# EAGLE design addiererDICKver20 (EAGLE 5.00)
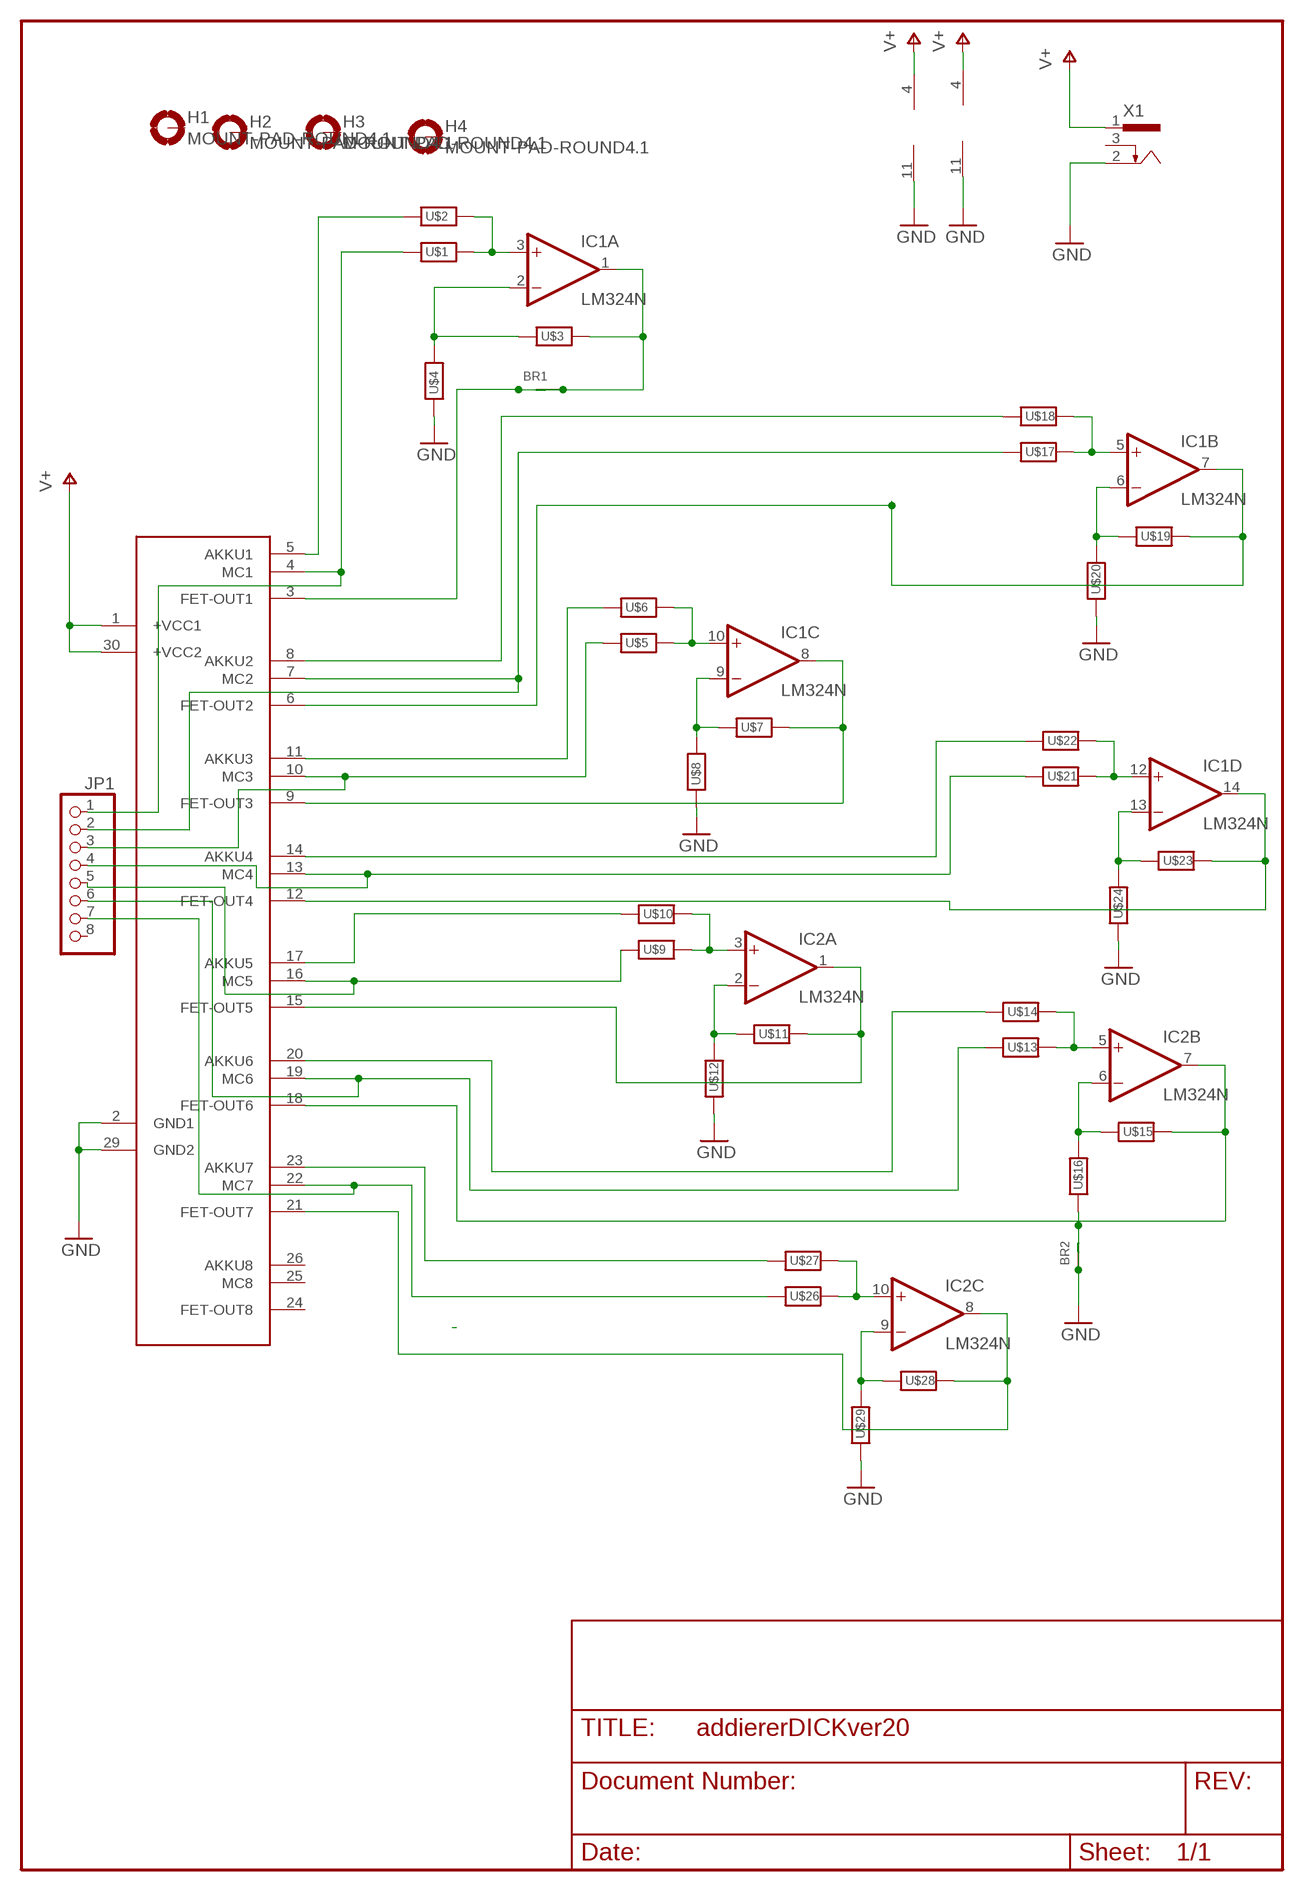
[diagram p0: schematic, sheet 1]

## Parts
BR1  BRUE3E  [BRUE3E]
BR2  BRUE8E  [BRUE8E]
H1  MOUNT-PAD-ROUND4.1  [4,1-PAD]
H2  MOUNT-PAD-ROUND4.1  [4,1-PAD]
H3  MOUNT-PAD-ROUND4.1  [4,1-PAD]
H4  MOUNT-PAD-ROUND4.1  [4,1-PAD]
IC1  LM324N  [DIL14]
IC2  LM324N  [DIL14]
JP1  PINHD-1X8  [1X08]
U$1  R4E  [R-4E]
U$2  R4E  [R-4E]
U$3  R4E  [R-4E]
U$4  R4E  [R-4E]
U$5  R4E  [R-4E]
U$6  R4E  [R-4E]
U$7  R4E  [R-4E]
U$8  R4E  [R-4E]
U$9  R4E  [R-4E]
U$10  R4E  [R-4E]
U$11  R4E  [R-4E]
U$12  R4E  [R-4E]
U$13  R4E  [R-4E]
U$14  R4E  [R-4E]
U$15  R4E  [R-4E]
U$16  R4E  [R-4E]
U$17  R4E  [R-4E]
U$18  R4E  [R-4E]
U$19  R4E  [R-4E]
U$20  R4E  [R-4E]
U$21  R4E  [R-4E]
U$22  R4E  [R-4E]
U$23  R4E  [R-4E]
U$24  R4E  [R-4E]
U$25  BALANCER1  [1X30]
U$26  R4E  [R-4E]
U$27  R4E  [R-4E]
U$28  R4E  [R-4E]
U$29  R4E  [R-4E]
X1  733980-62  [733980-62]

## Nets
AKKU23: U$22.1 U$25.14(AKKU4)
AKKU56: U$2.1 U$25.5(AKKU1)
GND: BR2.1 BR2.2 IC1.11(P:V-) IC2.11(P:V-) U$4.1 U$8.1 U$12.1 U$16.1 U$20.1 U$24.1 U$25.2(GND1) U$25.29(GND2) U$29.1 X1.2
N$1: IC1.3(A:+IN) U$1.2 U$2.2
N$2: IC1.2(A:-IN) U$3.1 U$4.2
N$3: BR1.1 BR1.2 IC1.1(A:OUT) U$3.2 U$25.3(FET-OUT1)
N$4: IC1.10(C:+IN) U$5.2 U$6.2
N$5: IC1.9(C:-IN) U$7.1 U$8.2
N$6: IC1.8(C:OUT) U$7.2 U$25.9(FET-OUT3)
N$7: IC2.3(A:+IN) U$9.2 U$10.2
N$8: IC2.2(A:-IN) U$11.1 U$12.2
N$9: IC2.1(A:OUT) U$11.2 U$25.15(FET-OUT5)
N$10: IC2.5(B:+IN) U$13.2 U$14.2
N$11: IC2.6(B:-IN) U$15.1 U$16.2
N$12: IC2.7(B:OUT) U$15.2 U$25.18(FET-OUT6)
N$13: IC1.5(B:+IN) U$17.2 U$18.2
N$14: IC1.6(B:-IN) U$19.1 U$20.2
N$15: IC1.7(B:OUT) U$19.2 U$25.6(FET-OUT2)
N$16: IC1.12(D:+IN) U$21.2 U$22.2
N$17: IC1.13(D:-IN) U$23.1 U$24.2
N$18: IC1.14(D:OUT) U$23.2 U$25.12(FET-OUT4)
N$19: U$18.1 U$25.8(AKKU2)
N$22: U$6.1 U$25.11(AKKU3)
N$25: U$10.1 U$25.17(AKKU5)
N$28: U$14.1 U$25.20(AKKU6)
N$30: IC2.10(C:+IN) U$26.2 U$27.2
N$31: IC2.9(C:-IN) U$28.1 U$29.2
N$32: IC2.8(C:OUT) U$25.21(FET-OUT7) U$28.2
N$33: U$25.23(AKKU7) U$27.1
N$36: JP1.1 U$1.1 U$25.4(MC1)
N$37: JP1.2 U$17.1 U$25.7(MC2)
N$38: JP1.3 U$5.1 U$25.10(MC3)
N$39: JP1.4 U$21.1 U$25.13(MC4)
N$40: JP1.7 U$25.22(MC7) U$26.1
N$41: JP1.6 U$13.1 U$25.19(MC6)
N$42: JP1.5 U$9.1 U$25.16(MC5)
V+: IC1.4(P:V+) IC2.4(P:V+) U$25.1(+VCC1) U$25.30(+VCC2) X1.1
Unconnected: H1.B4,1(MOUNT) H2.B4,1(MOUNT) H3.B4,1(MOUNT) H4.B4,1(MOUNT) IC2.12(D:+IN) IC2.13(D:-IN) IC2.14(D:OUT) JP1.8 U$25.24(FET-OUT8) U$25.25(MC8) U$25.26(AKKU8) X1.3

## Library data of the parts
BR1 = raf_discrete:BRUE3E
BR2 = raf_discrete:BRUE8E
H1-H4 = holes:MOUNT-PAD-ROUND: MOUNTING PAD, round
IC1 IC2 = linear:LM324: OP AMP
JP1 = pinhead:PINHD-1X8: PIN HEADER
U$1-U$24 U$26-U$29 = raf_discrete:R: Standard-Widerstand 1/4W, Baugrößen 4e - 8e
U$25 = balancer-mega8:BALANCER1
X1 = con-conrad:73398?: FEMALE PRINT CONNECTOR Niedervolt-Steckverbinder Distributor Conrad

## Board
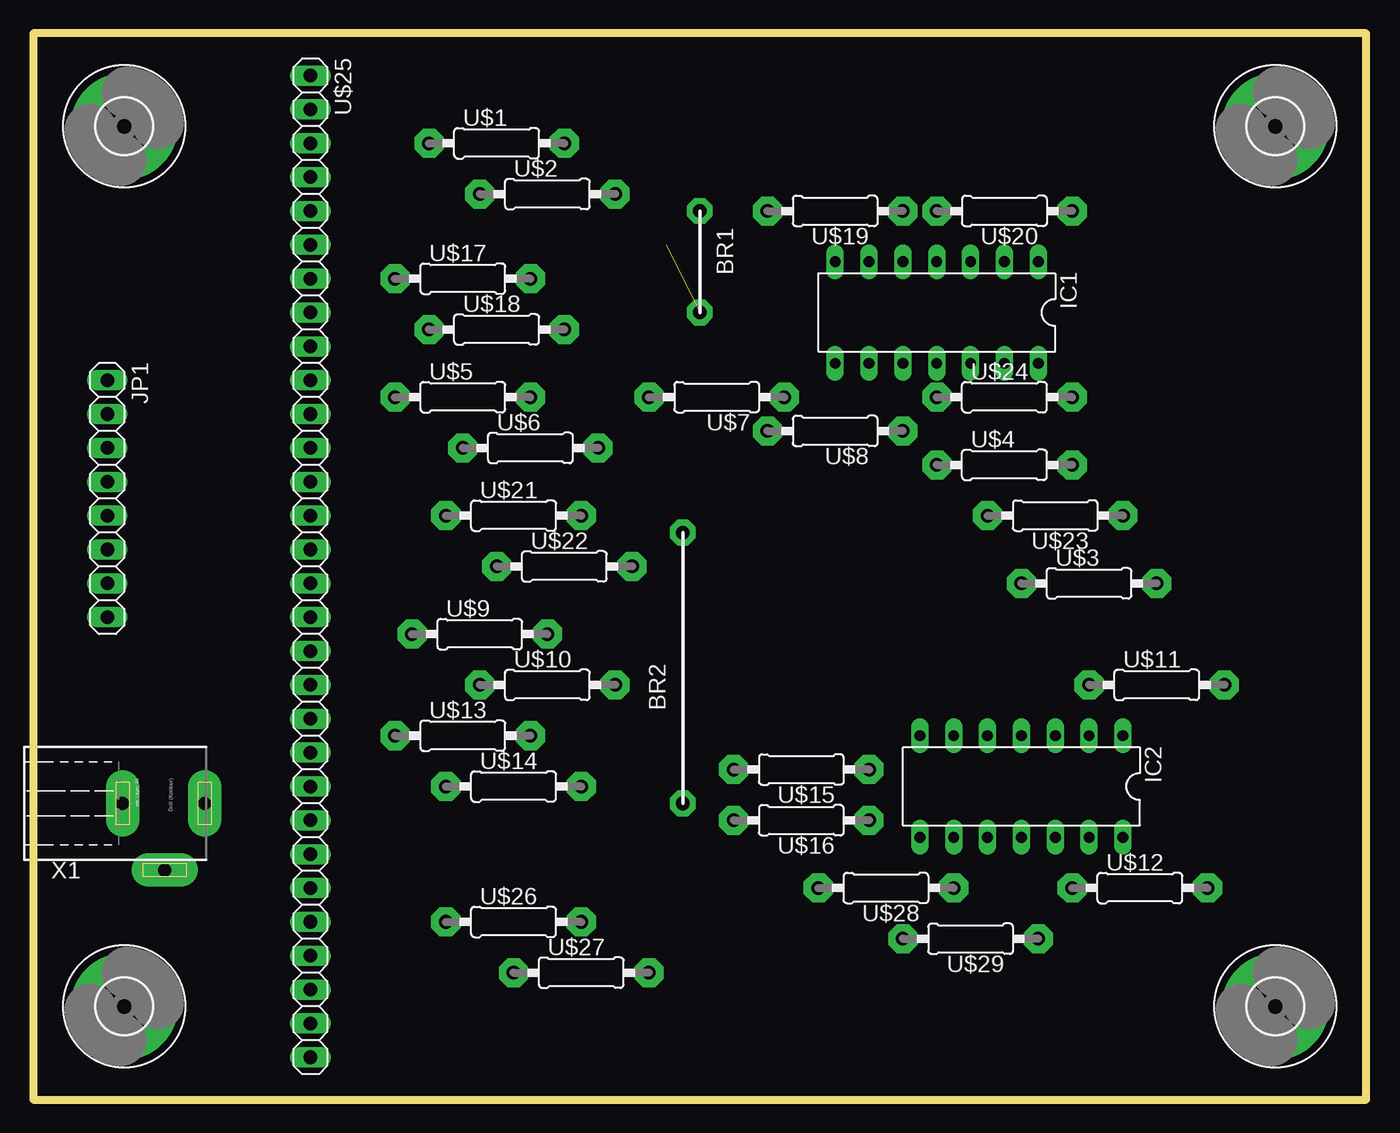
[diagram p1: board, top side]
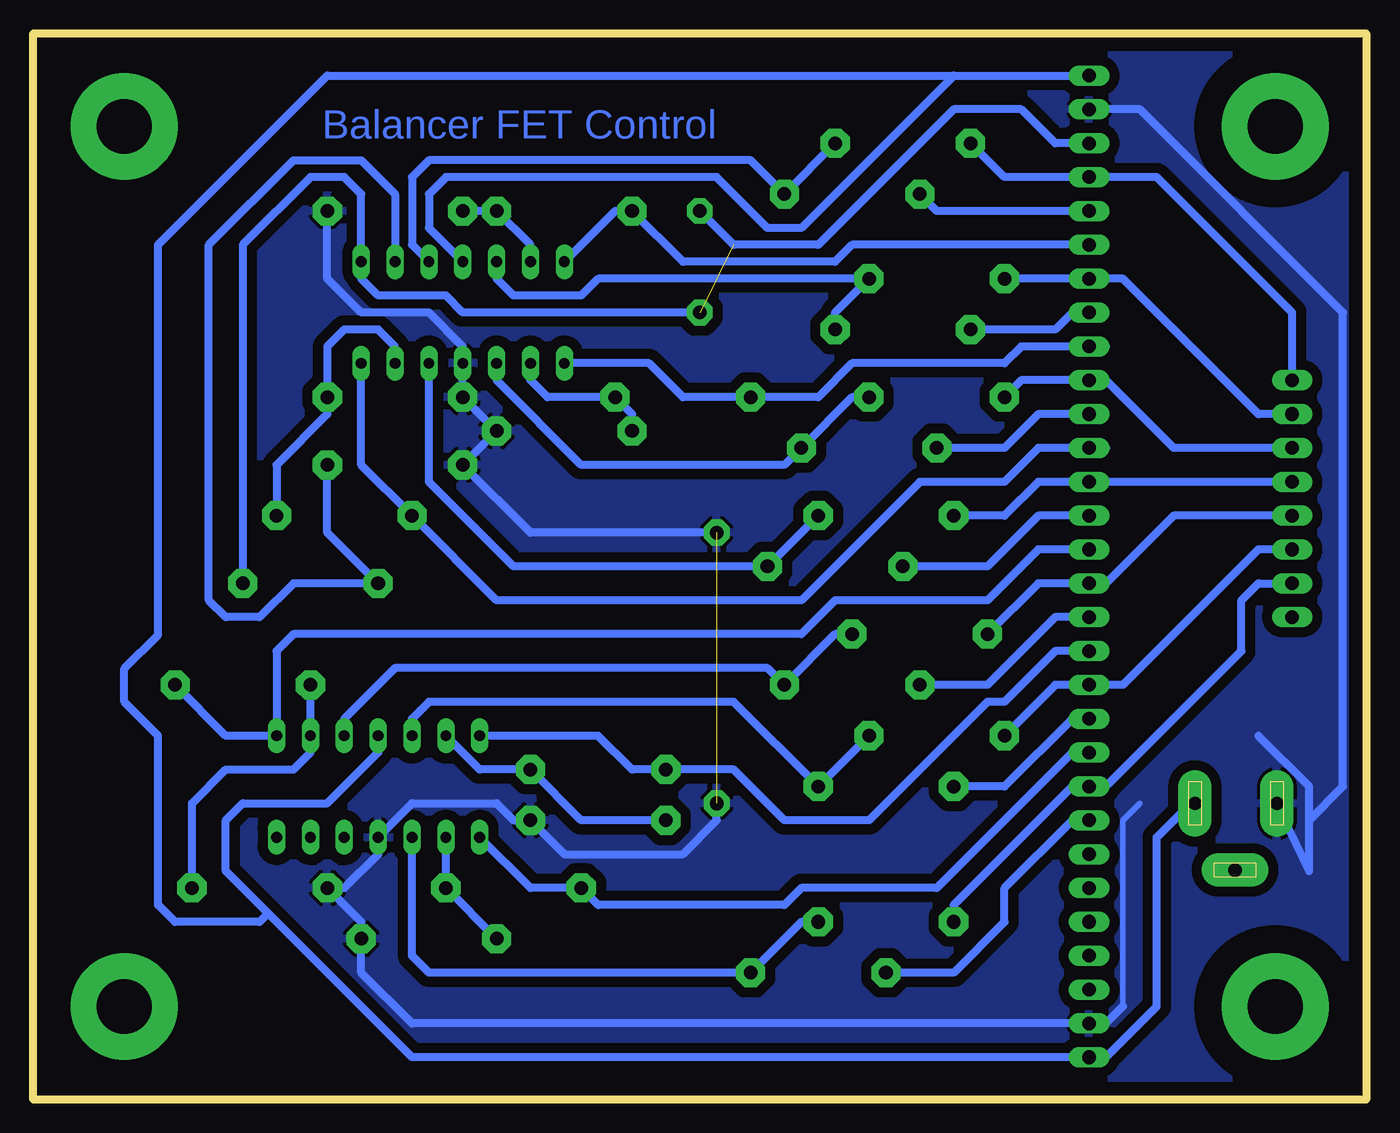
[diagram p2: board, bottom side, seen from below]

Size 100 x 80 mm. Coordinates in mm from the lower left corner, seen from the top.
Outline: 0,0 100,0 100,80 0,80 0,0
Copper layers (1*16): Top 0.035mm / dielectric 1.5mm / Bottom 0.035mm
Design rules "default *": minimum track width 10mil, minimum drill 24mil, track to track 30mil, track to pad 30mil, pad to pad 8mil, via to via 8mil, smd to smd 8mil, copper to edge 40mil, drill to drill 8mil, minimum pad ring 10mil, minimum via ring 8mil, stop-mask expansion 4mil, vias tented up to drill 0mil, thermal gap 10mil

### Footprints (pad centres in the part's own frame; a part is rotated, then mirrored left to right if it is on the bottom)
BRUE3E = drill 1.016 pad 1.93 octagon: 1 0,0; 2 7.62,0
BRUE8E = drill 1.016 pad 1.93 octagon: 1 0,0; 2 20.32,0
4,1-PAD = drill 4.1 pad 8 round: B4,1 0,0
DIL14 = drill 0.813 long: 1 -7.62,-3.81; 2 -5.08,-3.81; 3 -2.54,-3.81; 4 0,-3.81; 5 2.54,-3.81; 6 5.08,-3.81; 7 7.62,-3.81; 8 7.62,3.81; 9 5.08,3.81; 10 2.54,3.81; 11 0,3.81; 12 -2.54,3.81; 13 -5.08,3.81; 14 -7.62,3.81
1X08 = drill 1.016 long: 1 -8.89,0; 2 -6.35,0; 3 -3.81,0; 4 -1.27,0; 5 1.27,0; 6 3.81,0; 7 6.35,0; 8 8.89,0
R-4E = drill 1.016 pad 2.184 octagon: 1 -5.08,0; 2 5.08,0
1X30 = drill 1.016 long: 1 -36.83,0; 2 -34.29,0; 3 -31.75,0; 4 -29.21,0; 5 -26.67,0; 6 -24.13,0; 7 -21.59,0; 8 -19.05,0; 9 -16.51,0; 10 -13.97,0; 11 -11.43,0; 12 -8.89,0; 13 -6.35,0; 14 -3.81,0; 15 -1.27,0; 16 1.27,0; 17 3.81,0; 18 6.35,0; 19 8.89,0; 20 11.43,0; 21 13.97,0; 22 16.51,0; 23 19.05,0; 24 21.59,0; 25 24.13,0; 26 26.67,0; 27 29.21,0; 28 31.75,0; 29 34.29,0; 30 36.83,0
733980-62 = drill 1 pad 2.5 long: 1 0,8.57; 2 0,2.42; 3 5,5.57

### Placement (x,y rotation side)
BR1  50,66.67 270 top
BR2  48.73,22.22 90 top
H1  6.82,6.98 0 top
H2  93.18,6.98 0 top
H3  93.18,73.02 0 top
H4  6.82,73.02 0 top
IC1  67.78,59.05 180 top
IC2  74.13,23.49 180 top
JP1  5.55,45.08 270 top
U$1  34.76,71.75 0 top
U$2  38.57,67.94 0 top
U$3  79.21,38.73 0 top
U$4  72.86,47.62 0 top
U$5  32.22,52.7 0 top
U$6  37.3,48.89 0 top
U$7  51.27,52.7 180 top
U$8  60.16,50.16 180 top
U$9  33.49,34.92 0 top
U$10  38.57,31.11 0 top
U$11  84.29,31.11 0 top
U$12  83.02,15.87 0 top
U$13  32.22,27.3 0 top
U$14  36.03,23.49 0 top
U$15  57.62,24.76 180 top
U$16  57.62,20.95 180 top
U$17  32.22,61.59 0 top
U$18  34.76,57.78 0 top
U$19  60.16,66.67 180 top
U$20  72.86,66.67 180 top
U$21  36.03,43.81 0 top
U$22  39.84,40 0 top
U$23  76.67,43.81 180 top
U$24  72.86,52.7 0 top
U$25  20.79,40 270 top
U$26  36.03,13.33 0 top
U$27  41.11,9.52 0 top
U$28  63.97,15.87 180 top
U$29  70.32,12.06 180 top
X1  4.28,22.22 270 top

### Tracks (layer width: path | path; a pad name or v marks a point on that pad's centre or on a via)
AKKU23
  Bottom 0.61: U$25.14 24.6,43.81 28.41,40 U$22.1
AKKU56
  Bottom 0.61: U$25.5 32.22,66.67 U$2.1
GND  (1 unrouted)
  Bottom 0.406: 18.25,6.98 18.25,20.95 16.98,22.22
  Bottom 0.61: BR2.2 62.7,42.54 U$4.1 U$8.1 U$24.1 IC1.11 67.78,56.51 70.32,59.05 75.4,59.05 77.94,61.59 U$20.1 | 4.28,17.14 X1.2 | 4.28,17.14 4.28,20.95 1.74,23.49 1.74,59.05 16.98,74.29 U$25.2 | 4.28,17.14 4.28,23.49 8.09,27.3 | 18.25,6.98 19.52,5.71 U$25.29 71.59,5.71 75.4,9.52 U$29.1 75.4,13.33 U$12.1 76.67,15.87 74.13,18.41 IC2.11 71.59,22.22 65.24,22.22 63.97,20.95 U$16.1 60.16,18.41 51.27,18.41 48.73,20.95 BR2.1
  pour Bottom: 0.47,79.37 99.53,79.37 99.53,0.63 0.47,0.63
N$1
  Bottom 0.61: IC1.3 71.59,64.13 71.59,69.21 70.32,70.48 46.19,70.48 U$2.2 U$1.2
N$2
  Bottom 0.61: U$4.2 77.94,42.54 U$3.1 80.48,38.73 83.02,36.19 85.56,36.19 86.83,37.46 86.83,64.13 80.48,70.48 75.4,70.48 72.86,67.94 IC1.2
N$3  (1 unrouted)
  Bottom 0.61: U$25.3 23.33,71.75 25.87,74.29 30.95,74.29 41.11,64.13 47.46,64.13 BR1.1 | BR1.2 67.78,59.05 69.05,60.32 74.13,60.32 75.4,61.59 IC1.1 75.4,67.94 76.67,69.21 79.21,69.21 84.29,64.13 U$3.2
N$4
  Bottom 0.61: U$5.2 38.57,52.7 U$6.2 43.65,47.62 58.89,47.62 65.24,53.97 IC1.10
N$5
  Bottom 0.61: U$8.2 55.08,51.43 U$7.1 61.43,52.7 62.7,53.97 IC1.9
N$6
  Bottom 0.61: 19.52,56.51 U$25.9 25.87,56.51 27.14,55.24 38.57,55.24 41.11,52.7 U$7.2 51.27,52.7 53.81,55.24 IC1.8
N$7
  Bottom 0.61: U$9.2 39.84,34.92 U$10.2 44.92,32.38 72.86,32.38 76.67,28.57 IC2.3
N$8
  Bottom 0.61: U$11.1 IC2.2 79.21,26.03 80.48,24.76 85.56,24.76 88.1,22.22 U$12.2
N$9
  Bottom 0.61: U$11.2 85.56,27.3 IC2.1 81.75,33.65 80.48,34.92 42.38,34.92 39.84,37.46 28.41,37.46 24.6,41.27 U$25.15
N$10
  Bottom 0.61: IC2.5 71.59,28.57 70.95,29.2 70.32,29.84 47.46,29.84 U$14.2 U$13.2
N$11
  Bottom 0.61: IC2.6 66.51,24.76 U$15.1 58.89,20.95 U$16.2
N$12
  Bottom 0.61: IC2.7 57.62,27.3 55.08,24.76 U$15.2 47.46,24.76 43.65,20.95 37.3,20.95 28.41,29.84 27.14,29.84 23.33,33.65 U$25.18
N$13
  Bottom 0.61: IC1.5 65.24,61.59 63.97,60.32 58.89,60.32 57.62,61.59 U$17.2 39.84,59.05 U$18.2
N$14
  Bottom 0.61: IC1.6 62.7,64.13 U$19.1 U$20.2
N$15
  Bottom 0.61: IC1.7 56.35,66.67 U$19.2 51.27,62.86 39.84,62.86 38.57,64.13 U$25.6
N$16
  Bottom 0.61: IC1.12 70.32,46.35 63.97,40 U$22.2 U$21.2
N$17
  Bottom 0.61: IC1.13 72.86,56.51 74.13,57.78 76.67,57.78 77.94,56.51 U$24.2 77.94,51.43 81.75,47.62 U$23.1
N$18
  Bottom 0.61: 19.52,48.89 U$25.12 24.6,48.89 27.14,46.35 33.49,46.35 42.38,37.46 65.24,37.46 U$23.2 75.4,47.62 IC1.14
N$19
  Bottom 0.61: U$25.8 22.06,59.05 23.33,57.78 U$18.1
N$22
  Bottom 0.61: U$25.11 24.6,51.43 27.14,48.89 U$6.1
N$25
  Bottom 0.61: U$25.17 23.33,36.19 28.41,31.11 U$10.1
N$28
  Bottom 0.61: U$25.20 22.06,28.57 27.14,23.49 U$14.1
N$30
  Bottom 0.61: U$26.2 42.38,13.33 U$27.2 70.32,9.52 71.59,10.79 IC2.10
N$31
  Bottom 0.61: IC2.9 U$28.1 U$29.2
N$32
  Bottom 0.61: U$25.21 22.06,26.03 32.22,15.87 42.38,15.87 43.65,14.6 57.62,14.6 U$28.2 62.7,15.87 IC2.8
N$33
  Bottom 0.61: U$25.23 22.06,20.95 27.14,15.87 27.14,13.33 30.95,9.52 U$27.1
N$36
  Bottom 0.61: U$1.1 27.14,69.21 U$25.4 15.71,69.21 5.55,59.05 JP1.1
N$37
  Bottom 0.61: U$17.1 U$25.7 18.25,61.59 8.09,51.43 JP1.2
N$38
  Bottom 0.61: U$5.1 25.87,53.97 U$25.10 19.52,53.97 14.44,48.89 JP1.3
N$39
  Bottom 0.61: U$21.1 27.14,43.81 24.6,46.35 U$25.13 JP1.4
N$40
  Bottom 0.61: U$26.1 30.95,14.6 22.06,23.49 U$25.22 19.52,23.49 9.36,33.65 9.36,37.46 8.09,38.73 JP1.7
N$41
  Bottom 0.61: U$13.1 23.33,31.11 U$25.19 18.25,31.11 8.09,41.27 JP1.6
N$42
  Bottom 0.61: U$9.1 24.6,38.73 U$25.16 19.52,38.73 14.44,43.81 JP1.5
V+
  Bottom 0.61: IC2.4 74.13,26.03 77.94,22.22 84.29,22.22 85.56,20.95 85.56,17.14 82.39,13.97 | IC1.4 70.32,65.4 70.32,67.94 69.05,69.21 48.73,69.21 44.92,65.4 42.38,65.4 30.95,76.83 | 30.95,76.83 U$25.1 | 30.95,76.83 77.94,76.83 90.64,64.13 90.64,34.87 93.18,32.33 93.18,29.84 90.64,27.3 90.64,14.6 89.37,13.33 83.02,13.33 82.39,13.97 | 82.39,13.97 71.59,3.17 U$25.30 19.52,3.17 15.71,6.98 15.71,19.68 13.17,22.22 X1.1

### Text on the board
Bottom: Balancer FET Control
